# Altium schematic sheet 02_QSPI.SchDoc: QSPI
size A4; Date: 9/24/2014; Author: P.A.; CompanyName: STMicroelectronics; Organization: Microcontrollers Division; Address1: 12, Rue Jules HOROWITZ; Address2: 38019 Grenoble; Address3: FRANCE; DocumentNumber: 5; Revision: E-01; SheetNumber: 5; SheetTotal: 12; Project: STM32F413H-DISCO
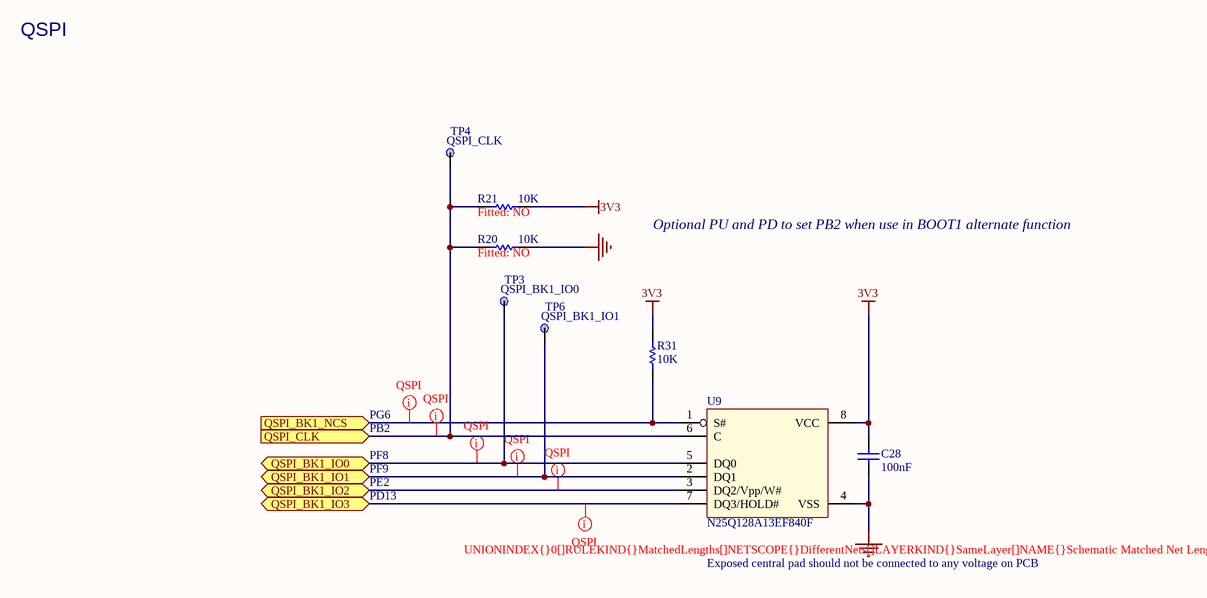
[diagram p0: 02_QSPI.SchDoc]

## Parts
C28  100nF  [C0402]
R20  10K  Fitted: NO  [R0402]
R21  10K  Fitted: NO  [R0402]
R31  10K  [R0402]
TP3  value QSPI_BK1_IO0  [TP_SMD_1MM]  (hidden comment: TP)
TP4  value QSPI_CLK  [TP_SMD_1MM]  (hidden comment: TP)
TP6  value QSPI_BK1_IO1  [TP_SMD_1MM]  (hidden comment: TP)
U9  N25Q128A13EF840F  [ICC_V-PDFN-8_8X6_P127]

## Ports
QSPI_BK1_IO0 (bidir), QSPI_BK1_IO1 (bidir), QSPI_BK1_IO2 (bidir), QSPI_BK1_IO3 (bidir), QSPI_BK1_NCS (in), QSPI_CLK (in)

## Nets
3V3: C28.2 R21.2 R31.2 U9.8(VCC)
GND: C28.1 R20.2 U9.4(VSS)
QSPI_BK1_IO0: TP3.1 U9.5(DQ0) ; port QSPI_BK1_IO0
QSPI_BK1_IO1: TP6.1 U9.2(DQ1) ; port QSPI_BK1_IO1
QSPI_BK1_IO2: U9.3(DQ2/Vpp/W#) ; port QSPI_BK1_IO2
QSPI_BK1_IO3: U9.7(DQ3/HOLD#) ; port QSPI_BK1_IO3
QSPI_BK1_NCS: R31.1 U9.1(S#) ; port QSPI_BK1_NCS
QSPI_CLK: R20.1 R21.1 TP4.1 U9.6(C) ; port QSPI_CLK

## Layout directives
rule Matched Net Lengths [Tolerance = 5mm]: QSPI_BK1_IO0, QSPI_BK1_IO1, QSPI_BK1_IO2, QSPI_BK1_IO3, QSPI_BK1_NCS, QSPI_CLK

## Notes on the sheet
- QSPI
- Optional PU and PD to set PB2 when use in BOOT1 alternate function
- PG6
- PB2
- PF8
- PF9
- PE2
- PD13
- Exposed central pad should not be connected to any voltage on PCB

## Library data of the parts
C28 = Cap_100nF_X7R_10%_0402: Capacitor,100nF,16V,X7R,10%,0402,YAGEO; Manuf_Part_1: CC0402KRX7R7BB104; Fitted: YES; Ordered_By: Subcon
R20 R21 = Res_10K_1%_0402: Resistor,10K,0402,1%,YAGEO; Manuf_Part_1: RC0402FR-0710KL; Ordered_By: subcon
R31 = Res_10K_1%_0402: Resistor,10K,0402,1%,YAGEO; Manuf_Part_1: RC0402FR-0710KL; Fitted: YES; Ordered_By: subcon
TP3 TP4 TP6 = TP 1mm: Test Point; Fitted: YES; Ordered_By: Subcon
U9 = N25Q128A13EF840F: 128Mb, 3V, Multiple I/O Serial Flash Memory, Quad/Dual; Manuf_1: MICRON; Manuf_Part_2: N25Q256A13EF840F; Manuf_Part_3: N25Q512A13GF840F; ECCN_US/EU: 3A991/NEC; Ref St: 9171973; Fitted: YES; Order_code: N25Q128A13EF840F-ND; Ordered_By: STM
